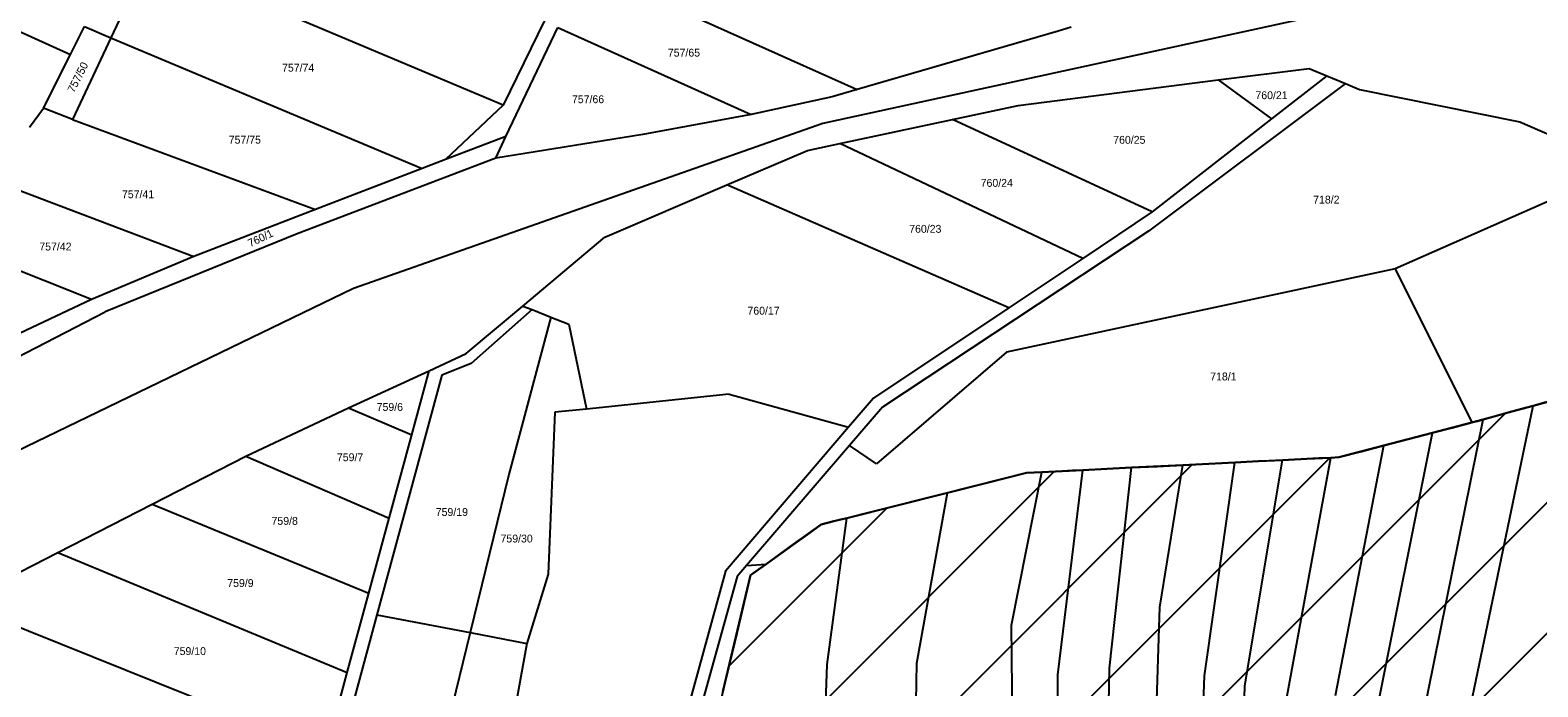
# Model space of a CAD drawing. Extents: x -593358 to -590116, y -1072518 to -1068420.
# Drawn here: x -591702.6 to -591376.8, y -1069932.5 to -1069790.6 of the extents above; entities that cross this region are included whole.
import ezdxf

# ---------------------------------------------------------------- set-up
doc = ezdxf.new("R2010")
doc.units = 0
for name, color, linetype in [('Parcela KN', 7, 'Continuous'), ('Parcela ZE', 7, 'Continuous'), ('Parcelní číslo', 7, 'Continuous'), ('Vnitřní obvod', 7, 'Continuous'), ('zastavitelné území', 7, 'Continuous'), ('Železnice', 7, 'Continuous')]:
    doc.layers.add(name, color=color, linetype=linetype)

msp = doc.modelspace()

# ---------------------------------------------------------------- linework, layer by layer
at = {"layer": 'Parcela KN'}
for p, q in [((-591680.57, -1069782.35), (-591685.17, -1069792.21)), ((-591480.45, -1069790.79), (-591523.93, -1069803.4)), ((-591477.64, -1069789.94), (-591480.45, -1069790.79)), ((-591685.17, -1069792.21), (-591693.43, -1069809.89)), ((-591489.1, -1069806.83), (-591445.88, -1069801.34)), ((-591445.88, -1069801.34), (-591426.23, -1069798.84)), ((-591445.88, -1069801.34), (-591434.37, -1069809.76)), ((-591422.39, -1069800.44), (-591434.37, -1069809.76)), ((-591426.23, -1069798.84), (-591422.39, -1069800.44)), ((-591422.39, -1069800.44), (-591418.37, -1069802.12)), ((-591529.31, -1069804.96), (-591546.81, -1069808.81)), ((-591523.93, -1069803.4), (-591529.31, -1069804.96)), ((-591418.37, -1069802.12), (-591460.93, -1069834.01)), ((-591418.37, -1069802.12), (-591415.37, -1069803.37)), ((-591415.37, -1069803.37), (-591380.71, -1069810.4)), ((-591503.29, -1069809.87), (-591489.1, -1069806.83)), ((-591693.43, -1069809.89), (-591640.94, -1069829.35)), ((-591546.81, -1069808.81), (-591570.19, -1069813.1)), ((-591527.66, -1069815.08), (-591503.29, -1069809.87)), ((-591434.37, -1069809.76), (-591460.16, -1069829.83)), ((-591380.71, -1069810.4), (-591357.96, -1069820.23)), ((-591599.81, -1069813.52), (-591612.84, -1069818.54)), ((-591570.19, -1069813.1), (-591602, -1069818.21)), ((-591602, -1069818.21), (-591599.81, -1069813.52)), ((-591602, -1069818.21), (-591644.94, -1069834.56)), ((-591552.06, -1069824.03), (-591534.64, -1069816.57)), ((-591534.64, -1069816.57), (-591527.66, -1069815.08)), ((-591617.92, -1069820.5), (-591640.94, -1069829.35)), ((-591612.84, -1069818.54), (-591617.92, -1069820.5)), ((-591357.96, -1069820.23), (-591407.62, -1069842.19)), ((-591578.45, -1069835.33), (-591552.06, -1069824.03)), ((-591640.94, -1069829.35), (-591667.26, -1069839.47)), ((-591460.16, -1069829.83), (-591475.16, -1069839.95)), ((-591460.93, -1069834.01), (-591518.43, -1069872.06)), ((-591644.94, -1069834.56), (-591686.41, -1069851.45)), ((-591596.12, -1069850.19), (-591578.45, -1069835.33)), ((-591667.26, -1069839.47), (-591689.34, -1069848.76)), ((-591475.16, -1069839.95), (-591491.1, -1069850.6)), ((-591407.62, -1069842.19), (-591491.64, -1069860.14)), ((-591407.62, -1069842.19), (-591391.1, -1069875.4)), ((-591689.34, -1069848.76), (-591710.91, -1069858.95)), ((-591608.36, -1069860.49), (-591596.12, -1069850.19)), ((-591596.12, -1069850.19), (-591594.14, -1069850.98)), ((-591491.1, -1069850.6), (-591520.38, -1069870.14)), ((-591772.61, -1069895.92), (-591686.41, -1069851.45)), ((-591590.1, -1069852.59), (-591599.19, -1069886.61)), ((-591594.14, -1069850.98), (-591590.1, -1069852.59)), ((-591590.1, -1069852.59), (-591586.23, -1069854.13)), ((-591586.23, -1069854.13), (-591582.42, -1069872.46)), ((-591616.39, -1069864.19), (-591608.36, -1069860.49)), ((-591491.64, -1069860.14), (-591519.71, -1069884.33)), ((-591633.79, -1069872.22), (-591616.39, -1069864.19)), ((-591355.32, -1069865.54), (-591377.81, -1069871.74)), ((-591551.55, -1069869.27), (-591582.42, -1069872.46)), ((-591551.55, -1069869.27), (-591525.75, -1069876.41)), ((-591520.38, -1069870.14), (-591525.75, -1069876.41)), ((-591655.99, -1069882.61), (-591633.79, -1069872.22)), ((-591589.2, -1069873.16), (-591590.66, -1069908.14)), ((-591582.42, -1069872.46), (-591589.2, -1069873.16)), ((-591518.43, -1069872.06), (-591525.54, -1069880.34)), ((-591377.81, -1069871.74), (-591388.65, -1069874.73)), ((-591525.75, -1069876.41), (-591552.34, -1069907.49)), ((-591391.1, -1069875.4), (-591399.57, -1069877.62)), ((-591388.65, -1069874.73), (-591391.1, -1069875.4)), ((-591399.57, -1069877.62), (-591410.09, -1069880.37)), ((-591676.25, -1069893), (-591655.99, -1069882.61)), ((-591525.54, -1069880.34), (-591547.83, -1069906.3)), ((-591519.71, -1069884.33), (-591525.54, -1069880.34)), ((-591421.52, -1069882.98), (-591431.98, -1069883.5)), ((-591419.74, -1069882.89), (-591421.52, -1069882.98)), ((-591410.09, -1069880.37), (-591419.74, -1069882.89)), ((-591599.19, -1069886.61), (-591607.55, -1069920.78)), ((-591487.28, -1069886.27), (-591504.39, -1069890.56)), ((-591484.01, -1069886.11), (-591487.28, -1069886.27)), ((-591475.12, -1069885.66), (-591484.01, -1069886.11)), ((-591464.61, -1069885.13), (-591475.12, -1069885.66)), ((-591453.54, -1069884.58), (-591464.61, -1069885.13)), ((-591442.32, -1069884.02), (-591453.54, -1069884.58)), ((-591431.98, -1069883.5), (-591442.32, -1069884.02)), ((-591696.65, -1069903.46), (-591676.25, -1069893)), ((-591504.39, -1069890.56), (-591526.14, -1069896.02)), ((-591526.14, -1069896.02), (-591531.69, -1069897.41)), ((-591531.69, -1069897.41), (-591543.59, -1069905.98)), ((-591717.93, -1069914.37), (-591696.65, -1069903.46)), ((-591547.83, -1069906.3), (-591543.59, -1069905.98)), ((-591543.59, -1069905.98), (-591546.92, -1069908.37)), ((-591590.66, -1069908.14), (-591595.27, -1069923.11)), ((-591552.34, -1069907.49), (-591560.96, -1069939.02)), ((-591546.92, -1069908.37), (-591558.95, -1069958.66)), ((-591549.86, -1069908.66), (-591557.17, -1069935.07)), ((-591547.83, -1069906.3), (-591549.86, -1069908.66)), ((-591607.55, -1069920.78), (-591620.65, -1069974.41)), ((-591595.27, -1069923.11), (-591598.27, -1069939.42))]:
    msp.add_line(p, q, dxfattribs=at)
at = {"layer": 'Parcela ZE'}
for p, q in [((-591600.37, -1069806.78), (-591678.38, -1069773.96)), ((-591580.4, -1069778.05), (-591523.93, -1069803.4)), ((-591727.98, -1069780.43), (-591693.93, -1069795.8)), ((-591591.48, -1069788.49), (-591600.37, -1069806.78)), ((-591693.93, -1069795.8), (-591690.9, -1069789.8)), ((-591690.9, -1069789.8), (-591685.17, -1069792.21)), ((-591599.81, -1069813.52), (-591588.57, -1069789.96)), ((-591588.57, -1069789.96), (-591546.81, -1069808.81)), ((-591685.17, -1069792.21), (-591617.92, -1069820.5)), ((-591699.76, -1069807.41), (-591693.93, -1069795.8)), ((-591702.75, -1069811.5), (-591699.76, -1069807.41)), ((-591693.43, -1069809.89), (-591699.76, -1069807.41)), ((-591600.37, -1069806.78), (-591612.84, -1069818.54)), ((-591460.16, -1069829.83), (-591503.29, -1069809.87)), ((-591475.16, -1069839.95), (-591527.66, -1069815.08)), ((-591710.7, -1069822.98), (-591667.26, -1069839.47)), ((-591491.1, -1069850.6), (-591552.06, -1069824.03)), ((-591689.34, -1069848.76), (-591721.42, -1069836.06)), ((-591594.14, -1069850.98), (-591607.3, -1069862.64)), ((-591607.3, -1069862.64), (-591613.63, -1069865.14)), ((-591613.63, -1069865.14), (-591627.69, -1069916.96)), ((-591620.14, -1069878.02), (-591616.39, -1069864.19)), ((-591633.79, -1069872.22), (-591620.14, -1069878.02)), ((-591392.29, -1069941.32), (-591377.81, -1069871.74)), ((-591401.83, -1069940.14), (-591388.65, -1069874.73)), ((-591625.02, -1069896.01), (-591620.14, -1069878.02)), ((-591411.76, -1069938.44), (-591399.57, -1069877.62)), ((-591655.99, -1069882.61), (-591625.02, -1069896.01)), ((-591431.32, -1069936.42), (-591421.52, -1069882.98)), ((-591420.54, -1069934.38), (-591410.09, -1069880.37)), ((-591490.54, -1069919.19), (-591484.01, -1069886.11)), ((-591480.52, -1069929.92), (-591475.12, -1069885.66)), ((-591469.37, -1069928.48), (-591464.61, -1069885.13)), ((-591458.46, -1069915.3), (-591453.54, -1069884.58)), ((-591448.84, -1069930.15), (-591442.32, -1069884.02)), ((-591440.14, -1069932.27), (-591431.98, -1069883.5)), ((-591676.25, -1069893), (-591629.43, -1069912.25)), ((-591510.97, -1069927.37), (-591504.39, -1069890.56)), ((-591629.43, -1069912.25), (-591625.02, -1069896.01)), ((-591530.35, -1069927.69), (-591526.14, -1069896.02)), ((-591696.65, -1069903.46), (-591634.08, -1069929.39)), ((-591634.08, -1069929.39), (-591629.43, -1069912.25)), ((-591717.93, -1069914.37), (-591638.65, -1069946.22)), ((-591461.35, -1069999.25), (-591458.46, -1069915.3)), ((-591627.69, -1069916.96), (-591641.49, -1069967.83)), ((-591627.69, -1069916.96), (-591607.55, -1069920.78)), ((-591489.93, -1069987.1), (-591490.54, -1069919.19)), ((-591607.55, -1069920.78), (-591595.27, -1069923.11)), ((-591538.05, -1070120.55), (-591530.35, -1069927.69)), ((-591512.51, -1069999.23), (-591510.97, -1069927.37)), ((-591470.62, -1069999.04), (-591469.37, -1069928.48)), ((-591638.65, -1069946.22), (-591634.08, -1069929.39)), ((-591480.66, -1069998.95), (-591480.52, -1069929.92)), ((-591451.28, -1069999.2), (-591448.84, -1069930.15)), ((-591441.77, -1069999.02), (-591440.14, -1069932.27))]:
    msp.add_line(p, q, dxfattribs=at)
at = {"layer": 'Vnitřní obvod'}
for p, q in [((-591372.188, -1069870.19), (-591377.81, -1069871.74)), ((-591383.23, -1069873.235), (-591385.94, -1069873.982)), ((-591380.52, -1069872.488), (-591383.23, -1069873.235)), ((-591377.81, -1069871.74), (-591380.52, -1069872.488)), ((-591395.335, -1069876.51), (-591397.453, -1069877.065)), ((-591393.218, -1069875.955), (-591395.335, -1069876.51)), ((-591391.1, -1069875.4), (-591393.218, -1069875.955)), ((-591389.875, -1069875.065), (-591391.1, -1069875.4)), ((-591388.65, -1069874.73), (-591389.875, -1069875.065)), ((-591385.94, -1069873.982), (-591388.65, -1069874.73)), ((-591407.46, -1069879.683), (-591410.09, -1069880.37)), ((-591404.83, -1069878.995), (-591407.46, -1069879.683)), ((-591402.2, -1069878.308), (-591404.83, -1069878.995)), ((-591399.57, -1069877.62), (-591402.2, -1069878.308)), ((-591397.453, -1069877.065), (-591399.57, -1069877.62)), ((-591429.365, -1069883.37), (-591431.98, -1069883.5)), ((-591426.75, -1069883.24), (-591429.365, -1069883.37)), ((-591424.135, -1069883.11), (-591426.75, -1069883.24)), ((-591421.52, -1069882.98), (-591424.135, -1069883.11)), ((-591420.63, -1069882.935), (-591421.52, -1069882.98)), ((-591419.74, -1069882.89), (-591420.63, -1069882.935)), ((-591414.915, -1069881.63), (-591419.74, -1069882.89)), ((-591412.503, -1069881), (-591414.915, -1069881.63)), ((-591410.09, -1069880.37), (-591412.503, -1069881)), ((-591487.28, -1069886.27), (-591491.557, -1069887.343)), ((-591485.645, -1069886.19), (-591487.28, -1069886.27)), ((-591484.01, -1069886.11), (-591485.645, -1069886.19)), ((-591481.787, -1069885.998), (-591484.01, -1069886.11)), ((-591479.565, -1069885.885), (-591481.787, -1069885.998)), ((-591477.343, -1069885.772), (-591479.565, -1069885.885)), ((-591475.12, -1069885.66), (-591477.343, -1069885.772)), ((-591472.493, -1069885.528), (-591475.12, -1069885.66)), ((-591469.865, -1069885.395), (-591472.493, -1069885.528)), ((-591467.238, -1069885.262), (-591469.865, -1069885.395)), ((-591464.61, -1069885.13), (-591467.238, -1069885.262)), ((-591461.843, -1069884.992), (-591464.61, -1069885.13)), ((-591459.075, -1069884.855), (-591461.843, -1069884.992)), ((-591456.307, -1069884.718), (-591459.075, -1069884.855)), ((-591453.54, -1069884.58), (-591456.307, -1069884.718)), ((-591450.735, -1069884.44), (-591453.54, -1069884.58)), ((-591447.93, -1069884.3), (-591450.735, -1069884.44)), ((-591445.125, -1069884.16), (-591447.93, -1069884.3)), ((-591442.32, -1069884.02), (-591445.125, -1069884.16)), ((-591439.735, -1069883.89), (-591442.32, -1069884.02)), ((-591437.15, -1069883.76), (-591439.735, -1069883.89)), ((-591434.565, -1069883.63), (-591437.15, -1069883.76)), ((-591431.98, -1069883.5), (-591434.565, -1069883.63)), ((-591500.113, -1069889.488), (-591504.39, -1069890.56)), ((-591495.835, -1069888.415), (-591500.113, -1069889.488)), ((-591491.557, -1069887.343), (-591495.835, -1069888.415)), ((-591509.828, -1069891.925), (-591515.265, -1069893.29)), ((-591504.39, -1069890.56), (-591509.828, -1069891.925)), ((-591527.527, -1069896.367), (-591528.915, -1069896.715)), ((-591526.14, -1069896.02), (-591527.527, -1069896.367)), ((-591520.703, -1069894.655), (-591526.14, -1069896.02)), ((-591515.265, -1069893.29), (-591520.703, -1069894.655)), ((-591534.665, -1069899.552), (-591540.615, -1069903.837)), ((-591531.69, -1069897.41), (-591534.665, -1069899.552)), ((-591528.915, -1069896.715), (-591531.69, -1069897.41)), ((-591540.615, -1069903.837), (-591546.92, -1069908.37)), ((-591546.92, -1069908.37), (-591549.927, -1069920.943)), ((-591549.927, -1069920.943), (-591552.935, -1069933.515))]:
    msp.add_line(p, q, dxfattribs=at)
at = {"layer": 'zastavitelné území'}
for p, q in [((-591559.544, -1070077.359), (-591344.836, -1069862.651)), ((-591555.77, -1070101.87), (-591315.438, -1069861.538)), ((-591562.991, -1070052.522), (-591383.884, -1069873.416)), ((-591564.855, -1070026.102), (-591421.744, -1069882.991)), ((-591566.529, -1069999.491), (-591451.516, -1069884.479)), ((-591560.082, -1069964.761), (-591481.294, -1069885.973)), ((-591551.619, -1069928.013), (-591517.443, -1069893.837))]:
    msp.add_line(p, q, dxfattribs=at)
msp.add_lwpolyline([(-591552.935, -1069933.515), (-591546.92, -1069908.37), (-591545.255, -1069907.175), (-591543.59, -1069905.98), (-591537.64, -1069901.695), (-591531.69, -1069897.41), (-591528.915, -1069896.715), (-591526.14, -1069896.02), (-591515.265, -1069893.29), (-591504.39, -1069890.56), (-591495.835, -1069888.415), (-591487.28, -1069886.27), (-591485.645, -1069886.19), (-591484.01, -1069886.11), (-591479.565, -1069885.885), (-591475.12, -1069885.66), (-591469.865, -1069885.395), (-591464.61, -1069885.13), (-591459.075, -1069884.855), (-591453.54, -1069884.58), (-591447.93, -1069884.3), (-591442.32, -1069884.02), (-591437.15, -1069883.76), (-591431.98, -1069883.5), (-591426.75, -1069883.24), (-591421.52, -1069882.98), (-591419.74, -1069882.89), (-591414.915, -1069881.63), (-591410.09, -1069880.37), (-591404.83, -1069878.995), (-591399.57, -1069877.62), (-591395.335, -1069876.51), (-591391.1, -1069875.4), (-591389.875, -1069875.065), (-591388.65, -1069874.73), (-591383.23, -1069873.235), (-591377.81, -1069871.74), (-591366.565, -1069868.64)], dxfattribs=at)
at = {"layer": 'Železnice'}
msp.add_lwpolyline([(-591413.541, -1069785.129), (-591531.288, -1069810.752), (-591632.717, -1069846.424), (-591712.303, -1069884.858), (-591807.707, -1069942.888), (-591847.876, -1069971.525), (-591892.565, -1070007.699), (-591955.079, -1070063.719), (-591996.253, -1070106.424), (-592033.41, -1070152.395), (-592108.352, -1070256.773), (-592135.969, -1070299.729), (-592184.967, -1070375.944), (-592263.759, -1070488.889), (-592300.665, -1070532.851)], dxfattribs=at)

# ---------------------------------------------------------------- texts
at = {"layer": 'Parcelní číslo'}
for s, p in [('757/65', (-591564.806, -1069796.28)), ('757/74', (-591648.179, -1069799.54)), ('757/66', (-591585.529, -1069806.35)), ('760/21', (-591437.835, -1069805.48)), ('757/75', (-591659.696, -1069815.1)), ('760/25', (-591468.56, -1069815.12)), ('760/24', (-591497.203, -1069824.43)), ('757/41', (-591682.771, -1069826.89)), ('718/2', (-591425.355, -1069828.04)), ('760/23', (-591512.65, -1069834.36)), ('757/42', (-591700.633, -1069838.19)), ('760/17', (-591547.611, -1069852.05)), ('718/1', (-591447.604, -1069866.27)), ('759/6', (-591627.73, -1069872.86)), ('759/7', (-591636.32, -1069883.73)), ('759/8', (-591650.45, -1069897.48)), ('759/19', (-591614.961, -1069895.56)), ('759/30', (-591600.963, -1069901.3)), ('759/9', (-591660.02, -1069910.92)), ('759/10', (-591671.578, -1069925.63))]:
    msp.add_text(s, height=1.7, dxfattribs=at).set_placement(p)
for s, rotation, p in [('757/50', 63.19724, (-591693.127, -1069804.225)), ('760/1', 25.61121, (-591655.05, -1069837.508))]:
    msp.add_text(s, height=1.7, rotation=rotation, dxfattribs=at).set_placement(p)

doc.saveas('drawing.dxf')
